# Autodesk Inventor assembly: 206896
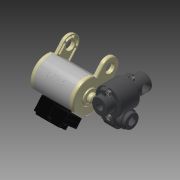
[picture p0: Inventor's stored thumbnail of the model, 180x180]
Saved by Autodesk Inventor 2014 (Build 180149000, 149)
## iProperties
Created: 2008-01
Part Number: 206896
Document SubType Name: Assembly
Designer: jjohnson
Mass: 119.186 g
Surface Area: 559.788 cm^2
Volume: 62.8758 cm^3
Density: 1.89557 g/cm^3
Author: jjohnson
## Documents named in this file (5)
- C:\Users\iTools\Desktop\tutorial files\Automotive\2000\206896.iam
- C:\Users\iTools\Desktop\tutorial files\Automotive\2000\200135.ipt
- C:\Users\iTools\Desktop\tutorial files\Automotive\2000\200678.ipt
- C:\Users\iTools\Desktop\tutorial files\Automotive\8000\801384.ipt
- C:\Users\iTools\Desktop\tutorial files\Automotive\9000\900402.iam
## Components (7 placed, 4 different names)
1. 200135:1 — Mate:1, Mate:12, Mate:3, Insert:1, Insert:2, Insert:3, Insert:4, Mate:11, Mate:10
2. AS 1427 - Metric M3 x 6:1 — Insert:1
3. AS 1427 - Metric M3 x 6:2 — Insert:2
4. AS 1427 - Metric M3 x 6:3 — Insert:3
5. AS 1427 - Metric M3 x 6:4 — Insert:4
6. 200678:1 — Mate:1, Mate:12, Mate:3, Mate:13
7. 900402:1 [sub-assembly] — Mate:11, Mate:10, Mate:13
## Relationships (10: Mate 6, Insert 4)
- Mate:1: 200135:1 ↔ 200678:1
- Mate:12: 200135:1 ↔ 200678:1
- Mate:3: 200135:1 ↔ 200678:1
- Insert:1: 200135:1 ↔ AS 1427 - Metric M3 x 6:1
- Insert:2: 200135:1 ↔ AS 1427 - Metric M3 x 6:2
- Insert:3: 200135:1 ↔ AS 1427 - Metric M3 x 6:3
- Insert:4: 200135:1 ↔ AS 1427 - Metric M3 x 6:4
- Mate:11: 200135:1 ↔ 900402:1
- Mate:10: 200135:1 ↔ 900402:1
- Mate:13: 200678:1 ↔ 900402:1
